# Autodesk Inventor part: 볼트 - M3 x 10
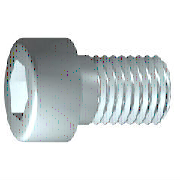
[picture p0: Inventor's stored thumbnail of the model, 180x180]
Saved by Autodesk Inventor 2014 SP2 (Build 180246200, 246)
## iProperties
Created: 2012-02
Part Number: 볼트 - M3 x 10
Material: 스테인리스강
Description: 6각 소켓 머리 캡 나사
Document SubType Name: Modeling
Standard: ISO 4762
Designer: mduedu
Standard Revision: Fourth edition 2004-03-01
Standards Organization: ISO
Language: ko-KR
Size Designation: M3 x 10
Categories: <MemberInstance><Categories><Category DisplayName="조임쇠" InternalName="e4da775c-781d-43d5-af7c-5136215cf5a6" Mnemonic="FSTN"><Category DisplayName="볼트" InternalN
Density: 7.75 g/cm^3
Appearance: 반광택
IsCustomPart: 0
Author: mduedu
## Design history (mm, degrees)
sketch "스케치1"
  geometry: L1 (-0.867, 0)-(10, 0); L2 (10, 0)-(10, 1.5); L3 (10, 1.5)-(1.25, 1.5); L4 (1.25, 1.5)-(0.943, 1.5); L5 (0.943, 1.5)-(0, 1.5); L6 (0, 1.5)-(0, 2.75); L7 (0, 2.75)-(-3, 2.75); L8 (-3, 2.75)-(-3, 1.443); L9 (-3, 1.443)-(-1.7, 1.443); L10 (-1.7, 1.443)-(-0.867, 0); L11 (-5.6, 0)-(12.6, 0) reference; L12 (0, -0.55)-(0, 3.3) reference; L13 (1.25, 1.5)-(0, 1.5)
  constraints: 22 end point, 6 parallel, 2 collinear, 2 perpendicular, 1 horizontal, 1 point on line
  dimensions: "d1" = 8.75 distance from line of L3.end L2 (= GEL); "d2" = 0.30683 distance of L4.end L3.end (computed from GAL); "d3" = 3 distance between parallel lines of L8 L6 (= KOH); "d4" = 1.3 distance of L8.end L9.end (= INTI); "d5" = 60 deg angle of L10 L1; "d6" = 3 diameter of L3 L1 (= GD); "d7" = 3 diameter of L5 L1 (= BDM); "d8" = 2.88675 diameter of L9 L1 (= 1.1547 x SW); "d9" = 5.5 diameter of L7 L1 (= KOD); "d26" = 10 distance between parallel lines of L12 L2 (= NLG)
revolve "본체" sketch "스케치1" stored, may be unused: angle "d10" = 90 deg
sketch "스케치2"
  geometry: L1 (0, -3.85)-(0, 3.85) reference; L2 (-3.85, 0)-(3.85, 0) reference; L3 (1.443, 0)-(0.722, -1.25); L4 (0.722, -1.25)-(-0.722, -1.25); L5 (-0.722, -1.25)-(-1.443, 0); L6 (-1.443, 0)-(-0.722, 1.25); L7 (-0.722, 1.25)-(0.722, 1.25); L8 (0.722, 1.25)-(1.443, 0); 2 further points
  constraints: 12 end point, 1 coincident, 1 horizontal alignment, 1 point on line, 12 other
extrude "슬롯" join sketch "스케치2" stored distance "d11" = 10; taper "d12" = 0 deg
workplane "Work Plane1"
fillet "Fillet2" dims "d30" = 0.1 (= R)
body "Solid1"
fillet "모깎기1" dims "d17" = 0.3 (= RR)
feature "스레드" dims "d13" = 8.75 (= GEL), "d14" = 0
chamfer "모따기1" distance "d15" = 0.30673 (= -0.5 x SPD + 0.5 x GD); stored, may be unused: second distance "d16" = 0.30673 (= GUL), angle "d27" = 45 deg
other parameters: "GD" = 3 [user parameter; used in 2 equation terms], "NLG" = 10 [user parameter; used in 1 equation term], "GEL" = 8.75 [user parameter; used in 2 equation terms], "KOD" = 5.5 [user parameter; used in 1 equation term], "KOH" = 3 [user parameter; used in 1 equation term], "INTI" = 1.3 [user parameter; used in 1 equation term], "GAL" = 0.30673 (= 0.61345 x PTC) [user parameter; used in 1 equation term], "GUL" = 0.30673 (= 0.61345 x PTC) [user parameter; used in 1 equation term], "BDM" = 3 (= NND) [user parameter; used in 1 equation term], "SW" = 2.5 [user parameter; used in 2 equation terms], "RR" = 0.3 [user parameter; used in 1 equation term], "SPD" = 2.38655 (= NND - 1.2269 x PTC) [user parameter; used in 1 equation term], "d19" = 0, "d28" = 0, "d29" = 0, "R" = 0.1 [user parameter; used in 1 equation term], "TOA" = 30 deg [user parameter], "GD1" = 2.38655 (= THREADDIA - 1.2269 x PTC) [user parameter], "THREADDIA" = 3 [user parameter; used in 1 equation term], "FAWI" = 45 deg [user parameter], "PTC" = 0.5 [user parameter; used in 5 equation terms], "NND" = 3 [user parameter; used in 2 equation terms], "E0" = 2.8875 (= 1.155 x SW) [user parameter]
